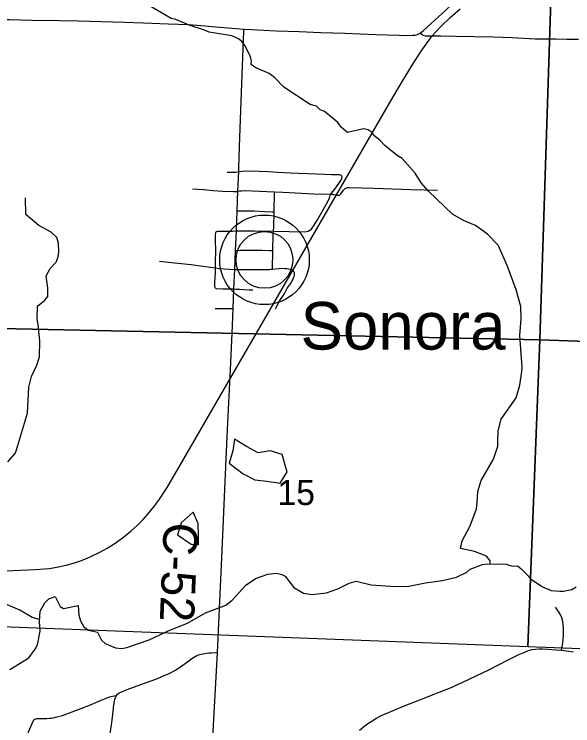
# Model space of a CAD drawing. Extents: x 0 to 34, y 0 to 22.
# Drawn here: x 5.686 to 6.614, y 17.641 to 18.823 of the extents above; entities that cross this region are included whole.
import ezdxf

# ---------------------------------------------------------------- set-up
doc = ezdxf.new("R2010")
doc.units = 0
for name, color, linetype in [('GM_X_County_Road', 7, 'Continuous'), ('GM_X_County_Road_Text', 7, 'Continuous'), ('GM_X_Minor_Lake', 7, 'Continuous'), ('GM_X_Minor_River', 7, 'Continuous'), ('GM_X_Rail_Line', 7, 'Continuous'), ('GM_X_Section', 7, 'Continuous'), ('GM_X_Section_Text', 7, 'Continuous'), ('GM_X_Township_Road', 7, 'Continuous'), ('GM_X_Unincorporated', 7, 'Continuous'), ('GM_X_Unincorporated_Location', 7, 'Continuous'), ('GM_X_Unincorporated_Text', 7, 'Continuous')]:
    doc.layers.add(name, color=color, linetype=linetype)

msp = doc.modelspace()

# ---------------------------------------------------------------- linework, layer by layer
at = {"layer": 'GM_X_County_Road'}
for p, q in [((6.0578, 18.5293), (6.059, 18.5619)), ((6.0565, 18.4966), (6.0578, 18.5293)), ((6.0552, 18.4632), (6.0565, 18.4966)), ((6.0539, 18.4307), (6.0552, 18.4632)), ((6.0526, 18.3994), (6.0539, 18.4307)), ((6.0511, 18.3668), (6.0526, 18.3994)), ((6.0497, 18.3345), (6.0511, 18.3668))]:
    msp.add_line(p, q, dxfattribs=at)
for points in [[(6.3605, 18.792), (6.3657, 18.7958), (6.3788, 18.8078), (6.403, 18.8302), (6.4124, 18.8389), (6.4218, 18.8466), (6.434, 18.8559), (6.4492, 18.8656), (6.4686, 18.8772), (6.4896, 18.8891), (6.5092, 18.9015), (6.541, 18.9239), (6.5806, 18.953)], [(5.604, 18.8143), (5.6049, 18.8143), (5.6235, 18.8148), (5.6359, 18.8147), (5.6547, 18.8147), (5.6782, 18.8145), (5.7153, 18.8135), (5.7611, 18.8129), (5.7927, 18.8123), (5.8306, 18.8111), (5.8691, 18.8101), (5.9006, 18.8092), (5.9419, 18.8076), (5.976, 18.8064), (6.0025, 18.8042), (6.027, 18.802), (6.0548, 18.7997), (6.0677, 18.7988)], [(6.059, 18.5619), (6.0592, 18.5694), (6.0599, 18.5849), (6.0604, 18.6038), (6.0641, 18.7085), (6.0676, 18.7955), (6.0677, 18.7988)], [(6.0677, 18.7988), (6.0804, 18.7979), (6.1215, 18.796), (6.1592, 18.7947), (6.1955, 18.7932), (6.2352, 18.7918), (6.2873, 18.7898), (6.3251, 18.7884), (6.342, 18.7883), (6.3479, 18.7884), (6.352, 18.7886), (6.356, 18.7897), (6.3605, 18.792)], [(6.3852, 18.7867), (6.3824, 18.7867), (6.3691, 18.7872), (6.3653, 18.7881), (6.3624, 18.7904), (6.3605, 18.792)], [(6.6234, 18.7813), (6.6041, 18.7817), (6.5855, 18.7819), (6.5518, 18.7821), (6.5135, 18.784), (6.4819, 18.7852), (6.4194, 18.7863), (6.3946, 18.7867), (6.3852, 18.7867)], [(6.0235, 17.762), (6.0273, 17.8356), (6.0314, 17.9319), (6.036, 18.0341), (6.0405, 18.1331), (6.0445, 18.2106), (6.0451, 18.2323), (6.0485, 18.3059), (6.0497, 18.3345)], [(6.0868, 17.4429), (6.0816, 17.454), (6.0731, 17.4704), (6.061, 17.4925), (6.024, 17.5571), (6.0214, 17.5627), (6.0193, 17.5684), (6.0175, 17.5743), (6.0163, 17.5803), (6.0155, 17.5863), (6.0152, 17.5925), (6.0157, 17.6111), (6.0186, 17.672), (6.0235, 17.762)]]:
    msp.add_lwpolyline(points, dxfattribs=at)
at = {"layer": 'GM_X_Minor_Lake'}
for points in [[(6.1373, 18.07), (6.1312, 18.0916), (6.1112, 18.0976), (6.0915, 18.0942), (6.0718, 18.1048), (6.0521, 18.1174), (6.0495, 18.0976), (6.0431, 18.0772), (6.0665, 18.0593), (6.0858, 18.0498), (6.1059, 18.0476), (6.1278, 18.0438), (6.1395, 18.0627), (6.1373, 18.07)], [(6.1373, 18.07), (6.1312, 18.0916), (6.1112, 18.0976), (6.0915, 18.0942), (6.0718, 18.1048), (6.0521, 18.1174), (6.0495, 18.0976)], [(6.0495, 18.0976), (6.0431, 18.0772), (6.0665, 18.0593), (6.0858, 18.0498), (6.1059, 18.0476), (6.1278, 18.0438), (6.1395, 18.0627), (6.1373, 18.07)], [(5.9923, 17.9417), (5.992, 17.9569), (5.9916, 17.977), (5.9833, 17.996), (5.9636, 17.9781), (5.9575, 17.958), (5.9799, 17.9425)], [(5.9922, 17.9426), (5.992, 17.9569), (5.9916, 17.977), (5.9833, 17.996), (5.9636, 17.9781), (5.9575, 17.958), (5.9799, 17.9425), (5.9923, 17.9417)], [(5.9799, 17.9425), (5.9923, 17.9417)]]:
    msp.add_lwpolyline(points, dxfattribs=at)
at = {"layer": 'GM_X_Minor_River'}
for points in [[(6.4769, 17.91), (6.477, 17.9151), (6.4709, 17.9227), (6.4505, 17.9305), (6.4274, 17.9354), (6.43, 17.9483), (6.4435, 17.973), (6.4539, 18.0015), (6.4554, 18.0114), (6.4564, 18.03), (6.4616, 18.0483), (6.4822, 18.0841), (6.4893, 18.1054), (6.4897, 18.1137), (6.4903, 18.1308), (6.4948, 18.1502), (6.52, 18.186), (6.5259, 18.2069), (6.5292, 18.2297), (6.5299, 18.2369), (6.5262, 18.2893), (6.528, 18.3174), (6.5275, 18.3375), (6.5202, 18.3655), (6.5052, 18.4057), (6.4899, 18.4394), (6.4721, 18.4579), (6.4523, 18.4722), (6.4322, 18.4808), (6.414, 18.491), (6.3741, 18.5291), (6.3623, 18.5431), (6.352, 18.559), (6.3303, 18.5835), (6.3224, 18.5888), (6.3015, 18.6054), (6.2935, 18.6141), (6.2833, 18.6216), (6.2806, 18.6269), (6.2741, 18.6311), (6.2666, 18.6329), (6.2397, 18.6267), (6.2299, 18.635), (6.2238, 18.6433), (6.2105, 18.6543), (6.2013, 18.6618), (6.1945, 18.6644), (6.1881, 18.6705), (6.1775, 18.6734), (6.1338, 18.7021), (6.1182, 18.7183), (6.1095, 18.7251), (6.0875, 18.7344), (6.0795, 18.7401), (6.0803, 18.7462), (6.0787, 18.7526), (6.0699, 18.7708), (6.0642, 18.778), (6.0585, 18.7825), (6.0475, 18.7874), (6.0097, 18.7936), (6.0021, 18.797), (5.9767, 18.8052), (5.9543, 18.8146), (5.9468, 18.8161), (5.8785, 18.8567)], [(5.6754, 18.0797), (5.6874, 18.0931), (5.6897, 18.0996), (5.7083, 18.1604), (5.7103, 18.2037), (5.7148, 18.2215), (5.7238, 18.2402), (5.7279, 18.2539), (5.7285, 18.2808), (5.7261, 18.3074), (5.7241, 18.318), (5.7248, 18.3381), (5.7369, 18.3481), (5.7417, 18.3545), (5.7421, 18.3682), (5.7389, 18.3887), (5.7457, 18.4009), (5.7555, 18.4112), (5.7588, 18.4203), (5.7603, 18.4287), (5.7598, 18.4427), (5.7571, 18.4522), (5.7473, 18.4612), (5.7272, 18.4725), (5.7055, 18.4906), (5.705, 18.5183)], [(5.8373, 17.7777), (5.8543, 17.7702), (5.8646, 17.7695), (5.8729, 17.7707), (5.9103, 17.7834), (5.9363, 17.7957), (5.942, 17.7988), (5.9737, 17.8115), (6.0039, 17.8287), (6.0378, 17.8414), (6.0484, 17.8498), (6.0706, 17.8746), (6.0868, 17.8857), (6.1076, 17.893), (6.1216, 17.8942), (6.1306, 17.8924), (6.136, 17.8894), (6.1504, 17.8709), (6.1664, 17.8615), (6.1807, 17.8589), (6.2046, 17.862), (6.2238, 17.8686), (6.2314, 17.8721), (6.2423, 17.8778), (6.254, 17.8813), (6.279, 17.8753), (6.3191, 17.8721), (6.3414, 17.8726), (6.3694, 17.8785), (6.3974, 17.8821), (6.4208, 17.8879), (6.4378, 17.8963), (6.4438, 17.9009), (6.4642, 17.9086), (6.4729, 17.9102), (6.5035, 17.9092), (6.5138, 17.9062), (6.5221, 17.9066), (6.5278, 17.9021), (6.5358, 17.8938), (6.5449, 17.8847), (6.5635, 17.8719), (6.5783, 17.8659), (6.5923, 17.8645), (6.5987, 17.8645), (6.6123, 17.8676), (6.6199, 17.8719)], [(5.7281, 17.8176), (5.716, 17.8207), (5.6952, 17.8331), (5.6406, 17.856)], [(5.6786, 17.7343), (5.7103, 17.7539), (5.7208, 17.7683), (5.7246, 17.7756), (5.7294, 17.798), (5.7278, 17.8143), (5.7292, 17.8314), (5.7367, 17.8451), (5.7435, 17.852), (5.7541, 17.8558), (5.7625, 17.8392), (5.7678, 17.8358), (5.7923, 17.8408), (5.7936, 17.8245), (5.7962, 17.8154), (5.8016, 17.8052), (5.8092, 17.7999), (5.8243, 17.7962), (5.8312, 17.783), (5.8373, 17.7777)]]:
    msp.add_lwpolyline(points, dxfattribs=at)
at = {"layer": 'GM_X_Rail_Line'}
msp.add_lwpolyline([(5.6713, 17.8983), (5.7208, 17.9005), (5.7439, 17.9024), (5.7594, 17.9049), (5.7725, 17.9079), (5.7862, 17.9118), (5.7978, 17.9157), (5.8109, 17.9209), (5.8285, 17.9293), (5.8406, 17.936), (5.8522, 17.9434), (5.8674, 17.9541), (5.8805, 17.9649), (5.8904, 17.9738), (5.9001, 17.9838), (5.9082, 17.9924), (5.9182, 18.0045), (5.9265, 18.016), (5.9399, 18.0371), (5.9533, 18.0598), (6.3156, 18.6859), (6.3294, 18.7093), (6.347, 18.7385), (6.3619, 18.7622), (6.3806, 18.7873), (6.3949, 18.8033), (6.4104, 18.8181), (6.4268, 18.8324)], dxfattribs=at)
at = {"layer": 'GM_X_Section'}
for points in [[(6.5918, 19.2905), (6.5595, 18.2824), (5.5833, 18.3028), (5.6189, 19.331)], [(6.5918, 19.2905), (7.6132, 19.2594), (7.5782, 18.246), (6.5595, 18.2824)], [(6.5595, 18.2824), (6.5395, 17.7719), (5.5625, 17.8089), (5.5833, 18.3028)], [(6.5595, 18.2824), (7.5782, 18.246), (7.5651, 17.7332), (6.5395, 17.7719)]]:
    msp.add_lwpolyline(points, close=True, dxfattribs=at)
at = {"layer": 'GM_X_Township_Road'}
for p, q in [((6.1177, 18.495), (6.1184, 18.5282)), ((6.115, 18.3999), (6.1156, 18.4306))]:
    msp.add_line(p, q, dxfattribs=at)
for points in [[(6.0398, 18.5608), (6.0437, 18.5607), (6.0502, 18.5608), (6.0545, 18.5611), (6.059, 18.5619)], [(6.059, 18.5619), (6.0648, 18.5627), (6.0706, 18.5631), (6.0931, 18.5626), (6.1079, 18.5618), (6.1235, 18.5611), (6.1453, 18.5601), (6.1578, 18.5595), (6.1734, 18.5588), (6.1878, 18.5581), (6.2023, 18.5575), (6.2129, 18.557), (6.2184, 18.5569), (6.2234, 18.5572), (6.2266, 18.5572), (6.2292, 18.5559), (6.2303, 18.5532), (6.2296, 18.5501), (6.2282, 18.5473), (6.2248, 18.542), (6.2183, 18.5326), (6.2144, 18.528), (6.2117, 18.5242)], [(5.9824, 18.5331), (6.001, 18.5319), (6.0165, 18.5307), (6.032, 18.5296), (6.0504, 18.5286), (6.0526, 18.5287), (6.0545, 18.5288), (6.0559, 18.529), (6.0578, 18.5293)], [(6.2117, 18.5242), (6.2153, 18.5241), (6.2164, 18.524), (6.2171, 18.5238), (6.2224, 18.5228), (6.2242, 18.5226), (6.2254, 18.5226), (6.2263, 18.5228), (6.2272, 18.5233), (6.2278, 18.5237), (6.2288, 18.5249), (6.2333, 18.5311), (6.2346, 18.5325), (6.2358, 18.5337), (6.2372, 18.5346), (6.2386, 18.5351), (6.2399, 18.5354), (6.2418, 18.5356)], [(6.2418, 18.5356), (6.2428, 18.5357), (6.2834, 18.5344), (6.3449, 18.532), (6.389, 18.5312)], [(6.0578, 18.5293), (6.0603, 18.5298), (6.0618, 18.53), (6.0634, 18.5301), (6.0688, 18.5302), (6.1184, 18.5282)], [(6.1166, 18.4627), (6.1686, 18.4617), (6.1716, 18.4622), (6.1746, 18.463), (6.1773, 18.4644), (6.1797, 18.4663), (6.1817, 18.4687), (6.1835, 18.4713), (6.1898, 18.4819), (6.2021, 18.5034), (6.2073, 18.512), (6.2098, 18.5181), (6.2104, 18.52), (6.211, 18.522), (6.2117, 18.5242)], [(6.1184, 18.5282), (6.1322, 18.5276), (6.1837, 18.5248), (6.2117, 18.5242)], [(6.0565, 18.4966), (6.0584, 18.4967), (6.0642, 18.4967), (6.0753, 18.4967), (6.0843, 18.4965), (6.1024, 18.4957), (6.1145, 18.4952), (6.1177, 18.495)], [(6.1166, 18.4627), (6.1171, 18.4697), (6.1177, 18.495)], [(6.0205, 18.4019), (6.0206, 18.4107), (6.0208, 18.431), (6.0204, 18.4474), (6.0206, 18.4563), (6.0208, 18.4606), (6.0214, 18.4623)], [(6.0214, 18.4623), (6.0239, 18.4628), (6.0366, 18.4627), (6.0489, 18.463), (6.0552, 18.4632)], [(6.0552, 18.4632), (6.0599, 18.4634), (6.0639, 18.4637), (6.0854, 18.4636), (6.1166, 18.4627)], [(6.1156, 18.4306), (6.1161, 18.4572), (6.1166, 18.4627)], [(6.0539, 18.4307), (6.0561, 18.4309), (6.0619, 18.4313), (6.0715, 18.4313), (6.0809, 18.4313), (6.088, 18.4314), (6.0974, 18.4312), (6.1109, 18.4308), (6.1156, 18.4306)], [(5.9273, 18.4129), (5.9522, 18.4105), (5.9802, 18.4074), (5.9919, 18.406), (6.0124, 18.4031), (6.0205, 18.4019)], [(6.0202, 18.3682), (6.0197, 18.3693), (6.0195, 18.3704), (6.0194, 18.3721), (6.0194, 18.3783), (6.0203, 18.3938), (6.0205, 18.4019)], [(6.0205, 18.4019), (6.0259, 18.401), (6.0526, 18.3994)], [(6.115, 18.3999), (6.1256, 18.401), (6.1309, 18.4012), (6.1359, 18.4011), (6.1389, 18.4009), (6.1417, 18.4004), (6.1438, 18.3999), (6.1457, 18.3994)], [(6.0526, 18.3994), (6.1083, 18.3993), (6.1104, 18.3994), (6.1126, 18.3996), (6.115, 18.3999)], [(6.12, 18.3337), (6.1228, 18.3393), (6.1276, 18.3477), (6.1343, 18.3581), (6.1392, 18.3668), (6.1414, 18.3702), (6.1437, 18.3738), (6.146, 18.3768), (6.1475, 18.3791), (6.1491, 18.3819), (6.1503, 18.3851), (6.1511, 18.3878), (6.1516, 18.3902), (6.1516, 18.3915), (6.1516, 18.3925), (6.1515, 18.3936), (6.1512, 18.3945), (6.1505, 18.396), (6.1493, 18.3975), (6.1474, 18.3987), (6.1457, 18.3994)], [(6.0202, 18.3682), (6.0211, 18.3677), (6.022, 18.3675), (6.0329, 18.3671), (6.0482, 18.3669), (6.0511, 18.3668)], [(6.0511, 18.3668), (6.0553, 18.3667), (6.0605, 18.3666), (6.0674, 18.3662), (6.0765, 18.3656), (6.0823, 18.3651)], [(6.0197, 18.3344), (6.0288, 18.3344), (6.0401, 18.3345), (6.0485, 18.3345), (6.0497, 18.3345)], [(6.5953, 17.7663), (6.597, 17.775), (6.5983, 17.7838), (6.5986, 17.7931), (6.5986, 17.8025), (6.5983, 17.8087), (6.5975, 17.8144), (6.5956, 17.8204), (6.5929, 17.8264), (6.5891, 17.8324), (6.5854, 17.8379)], [(6.2595, 17.6337), (6.2698, 17.6418), (6.2773, 17.6471), (6.2869, 17.6528), (6.2975, 17.6582), (6.3118, 17.6647), (6.3357, 17.6745), (6.3597, 17.6839), (6.3892, 17.6956), (6.4109, 17.7041), (6.4314, 17.7135), (6.4746, 17.7338), (6.5064, 17.7505), (6.5232, 17.7585), (6.5317, 17.7623), (6.5404, 17.7659), (6.5464, 17.7677), (6.552, 17.7683), (6.5576, 17.7687), (6.5641, 17.7687), (6.5732, 17.7682), (6.5858, 17.7673), (6.5953, 17.7663)], [(6.5953, 17.7663), (6.6151, 17.7638)], [(5.8558, 17.6913), (5.8574, 17.6932), (5.8602, 17.6954), (5.8632, 17.6968), (5.8737, 17.7014), (5.9027, 17.7114), (5.9229, 17.7191), (5.9313, 17.7225), (5.9436, 17.7279), (5.9538, 17.7333), (5.9646, 17.7402), (5.9764, 17.749), (5.9812, 17.7527), (5.9838, 17.7545), (5.9864, 17.7561), (5.9892, 17.7575), (5.9921, 17.7586), (5.9964, 17.7598), (6.0095, 17.7619), (6.0132, 17.7622), (6.018, 17.7624), (6.0235, 17.762)], [(5.7204, 17.652), (5.7217, 17.6526), (5.7237, 17.653), (5.7355, 17.6529), (5.7405, 17.653), (5.7446, 17.6533), (5.7473, 17.6536), (5.7508, 17.6541), (5.7571, 17.6556), (5.7663, 17.6581), (5.7779, 17.6623), (5.8099, 17.6747), (5.833, 17.6844), (5.8446, 17.689), (5.8491, 17.6902), (5.8558, 17.6913)], [(5.8457, 17.6273), (5.8478, 17.6423), (5.8493, 17.6545), (5.8518, 17.6759), (5.8528, 17.682), (5.8534, 17.685), (5.8543, 17.688), (5.8558, 17.6913)], [(5.6928, 17.5941), (5.7084, 17.6281), (5.7173, 17.6486), (5.7189, 17.6507), (5.7204, 17.652)]]:
    msp.add_lwpolyline(points, dxfattribs=at)
at = {"layer": 'GM_X_Unincorporated'}
for radius in [0.0744, 0.0472]:
    msp.add_circle((6.1018, 18.4152), radius, dxfattribs=at)
at = {"layer": 'GM_X_Unincorporated_Location'}
msp.add_line((6.1018, 18.4152), (6.1018, 18.4152), dxfattribs=at)

# ---------------------------------------------------------------- texts
at = {"layer": 'GM_X_County_Road_Text'}
msp.add_text('C-52', height=0.05682, rotation=267.6141, dxfattribs=at).set_placement((5.9347, 17.9794))
at = {"layer": 'GM_X_Section_Text'}
msp.add_text('15', height=0.04186, rotation=0, dxfattribs=at).set_placement((6.1234, 18.0076))
at = {"layer": 'GM_X_Unincorporated_Text'}
msp.add_text('Sonora', height=0.07898, rotation=0, dxfattribs=at).set_placement((6.1617, 18.2661))

doc.saveas('drawing.dxf')
